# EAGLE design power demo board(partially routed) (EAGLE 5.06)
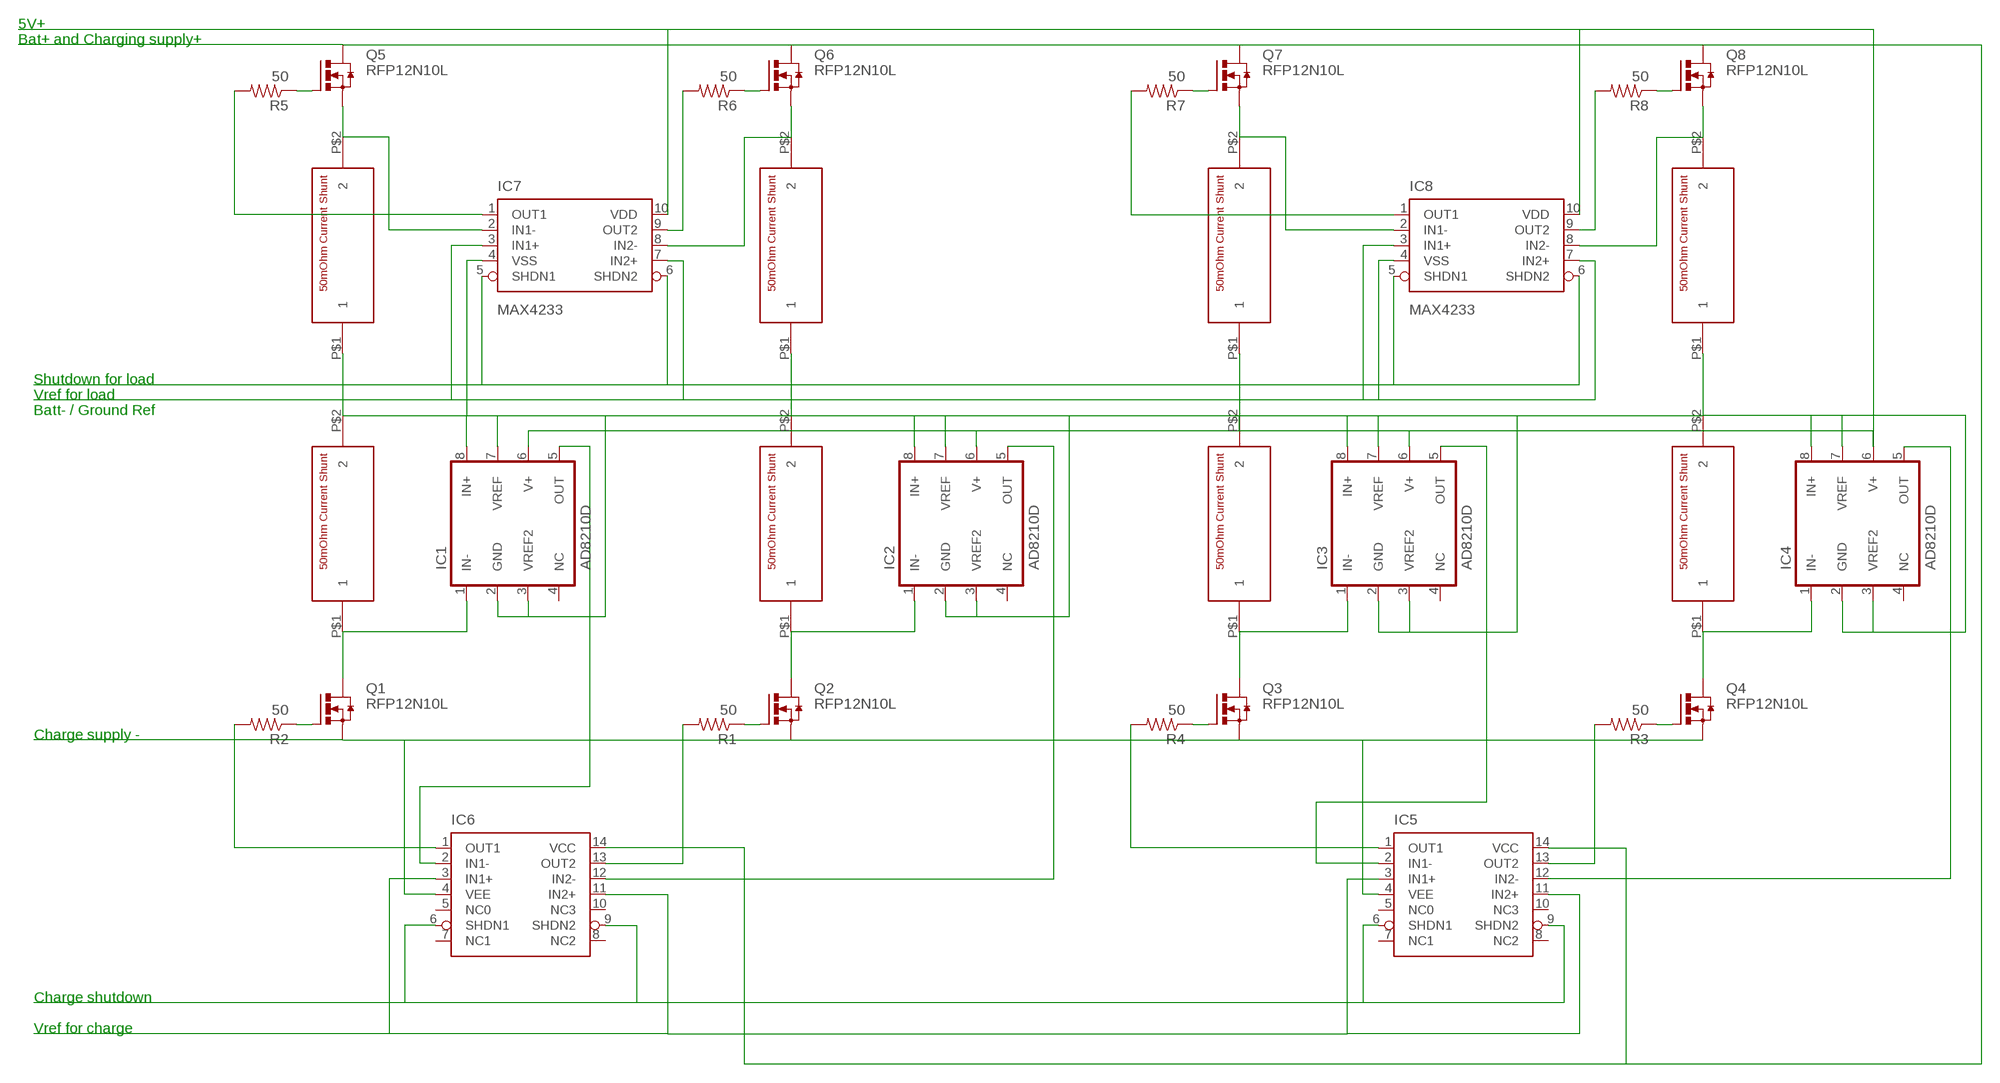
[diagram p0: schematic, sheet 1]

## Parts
IC1  AD8210D  [SO08]
IC2  AD8210D  [SO08]
IC3  AD8210D  [SO08]
IC4  AD8210D  [SO08]
IC5  MAX4168D  [SO14]
IC6  MAX4168D  [SO14]
IC7  MAX4233  [UMAX10]
IC8  MAX4233  [UMAX10]
Q1  RFP12N10L  [TO220-W/657-20ABP]
Q2  RFP12N10L  [TO220-W/657-20ABP]
Q3  RFP12N10L  [TO220-W/657-20ABP]
Q4  RFP12N10L  [TO220-W/657-20ABP]
Q5  RFP12N10L  [TO220-W/657-20ABP]
Q6  RFP12N10L  [TO220-W/657-20ABP]
Q7  RFP12N10L  [TO220-W/657-20ABP]
Q8  RFP12N10L  [TO220-W/657-20ABP]
R1  50  R-US_0207/10  [0207/10]
R2  50  R-US_0207/10  [0207/10]
R3  50  R-US_0207/10  [0207/10]
R4  50  R-US_0207/10  [0207/10]
R5  50  R-US_0207/10  [0207/10]
R6  50  R-US_0207/10  [0207/10]
R7  50  R-US_0207/10  [0207/10]
R8  50  R-US_0207/10  [0207/10]
U$1  630HR050E  [630HR050E]
U$2  630HR050E  [630HR050E]
U$3  630HR050E  [630HR050E]
U$4  630HR050E  [630HR050E]
U$5  630HR050E  [630HR050E]
U$6  630HR050E  [630HR050E]
U$7  630HR050E  [630HR050E]
U$8  630HR050E  [630HR050E]

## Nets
N$1: IC5.13(OUT2) R3.2
N$2: IC1.1(IN-) Q1.2(D) U$5.P$1
N$3: IC2.1(IN-) Q2.2(D) U$6.P$1
N$4: IC3.1(IN-) Q3.2(D) U$7.P$1
N$5: IC7.3(IN1+) IC7.7(IN2+) IC8.3(IN1+) IC8.4(VSS) IC8.7(IN2+)
N$6: IC5.4(VEE) IC6.4(VEE) Q1.3(S) Q2.3(S) Q3.3(S) Q4.3(S)
N$7: IC7.2(IN1-) Q5.3(S) U$1.P$2
N$8: IC7.8(IN2-) Q6.3(S) U$2.P$2
N$9: IC8.2(IN1-) Q7.3(S) U$3.P$2
N$10: IC8.8(IN2-) Q8.3(S) U$4.P$2
N$11: IC5.14(VCC) IC6.14(VCC) Q5.2(D) Q6.2(D) Q7.2(D) Q8.2(D)
N$12: IC7.1(OUT1) R5.2
N$13: Q5.1(G) R5.1
N$14: IC7.9(OUT2) R6.2
N$15: Q6.1(G) R6.1
N$16: Q7.1(G) R7.1
N$17: IC8.1(OUT1) R7.2
N$18: Q8.1(G) R8.1
N$19: IC8.9(OUT2) R8.2
N$20: IC7.5(SHDN1) IC7.6(SHDN2) IC8.5(SHDN1) IC8.6(SHDN2)
N$21: IC4.1(IN-) Q4.2(D) U$8.P$1
N$22: IC5.6(SHDN1) IC5.9(SHDN2) IC6.6(SHDN1) IC6.9(SHDN2)
N$23: IC6.13(OUT2) R1.2
N$24: Q1.1(G) R2.1
N$25: Q2.1(G) R1.1
N$26: Q3.1(G) R4.1
N$27: Q4.1(G) R3.1
N$28: IC5.1(OUT1) R4.2
N$29: IC2.5(OUT) IC6.12(IN2-)
N$31: IC5.3(IN1+) IC5.11(IN2+) IC6.3(IN1+) IC6.11(IN2+)
N$32: IC1.5(OUT) IC6.2(IN1-)
N$33: IC6.1(OUT1) R2.2
N$34: IC4.5(OUT) IC5.12(IN2-)
N$35: IC3.5(OUT) IC5.2(IN1-)
N$36: IC1.2(GND) IC1.3(VREF2) IC1.7(VREF) IC1.8(IN+) IC2.2(GND) IC2.3(VREF2) IC2.7(VREF) IC2.8(IN+) IC3.2(GND) IC3.3(VREF2) IC3.7(VREF) IC3.8(IN+) IC4.2(GND) IC4.3(VREF2) IC4.7(VREF) IC4.8(IN+) IC7.4(VSS) U$1.P$1 U$2.P$1 U$3.P$1 U$4.P$1 U$5.P$2 U$6.P$2 U$7.P$2 U$8.P$2
N$40: IC1.6(V+) IC2.6(V+) IC3.6(V+) IC4.6(V+) IC7.10(VDD) IC8.10(VDD)
Unconnected: IC5.5(NC0) IC5.7(NC1) IC5.10(NC3) IC6.5(NC0) IC6.7(NC1) IC6.10(NC3)

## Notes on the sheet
- 5V+
- Bat+ and Charging supply+
- Shutdown for load
- Vref for load
- Batt- / Ground Ref
- Charge supply -
- Charge shutdown
- Vref for charge

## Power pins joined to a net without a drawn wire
NC: IC1.4(NC) IC2.4(NC) IC3.4(NC) IC4.4(NC)
NC2: IC5.8(NC2) IC6.8(NC2)

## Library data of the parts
IC1-IC4 = NEWPARTS:AD8210: High Voltage, Bidirectional Current Shunt Monitor
IC5 IC6 = NEWPARTS:MAX4168: High-Output-Drive, Precision, Low-power, Single-Supply, Rail-to-Rail I/O Op Amps with Shutdown
IC7 IC8 = NEWPARTS:MAX4233: High-Output-Drive, 10MHz, 10V/us, Rail-to_rail I/O Op Amps with Shutdown in SC70
Q1-Q8 = NEWPARTS:RFP12N10L: N-Channel Power MOSFET 100V; 12A; 0,2Ohm< Logic Level
R1-R8 = rcl:R-US_: RESISTOR, American symbol
U$1-U$8 = NEWPARTS:630HR050E

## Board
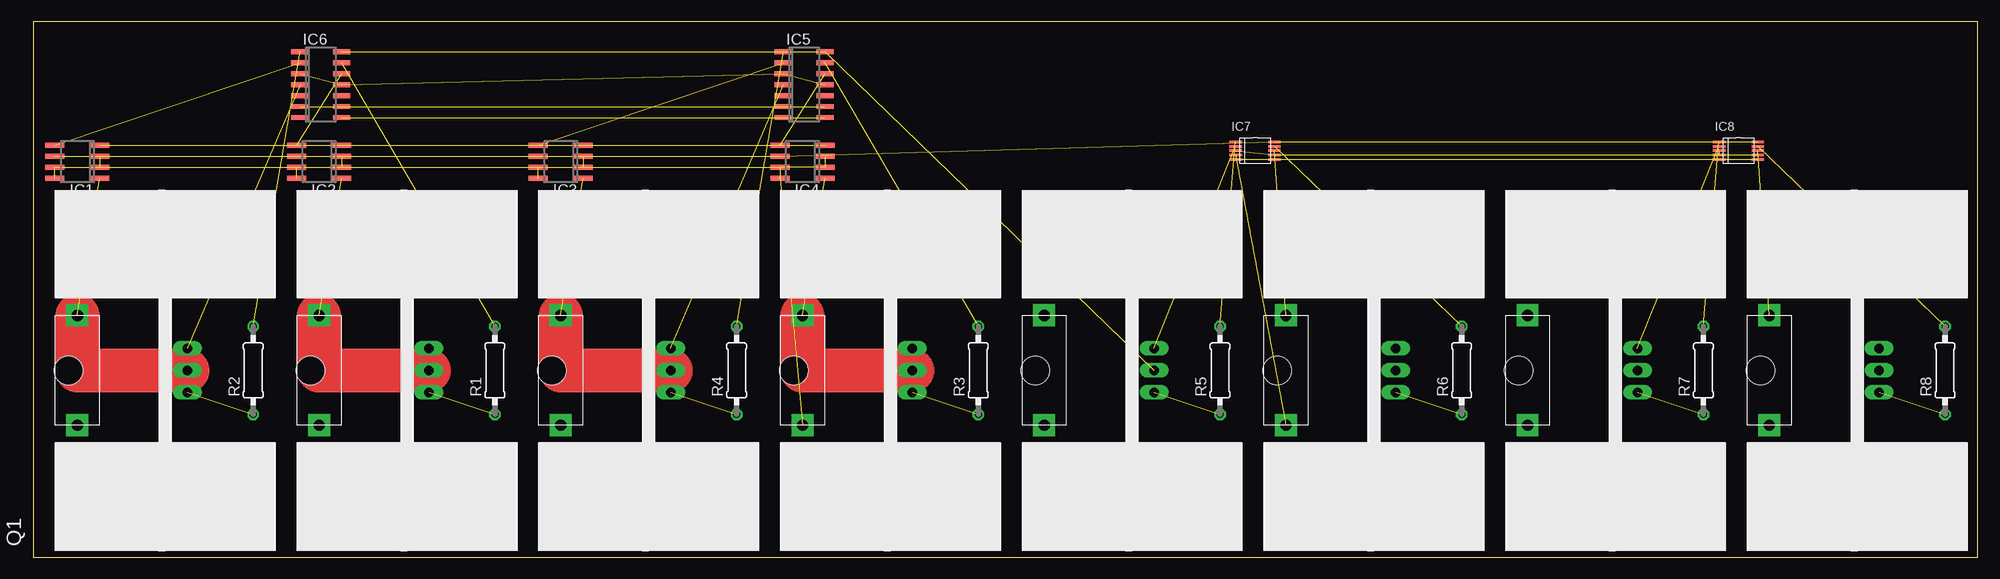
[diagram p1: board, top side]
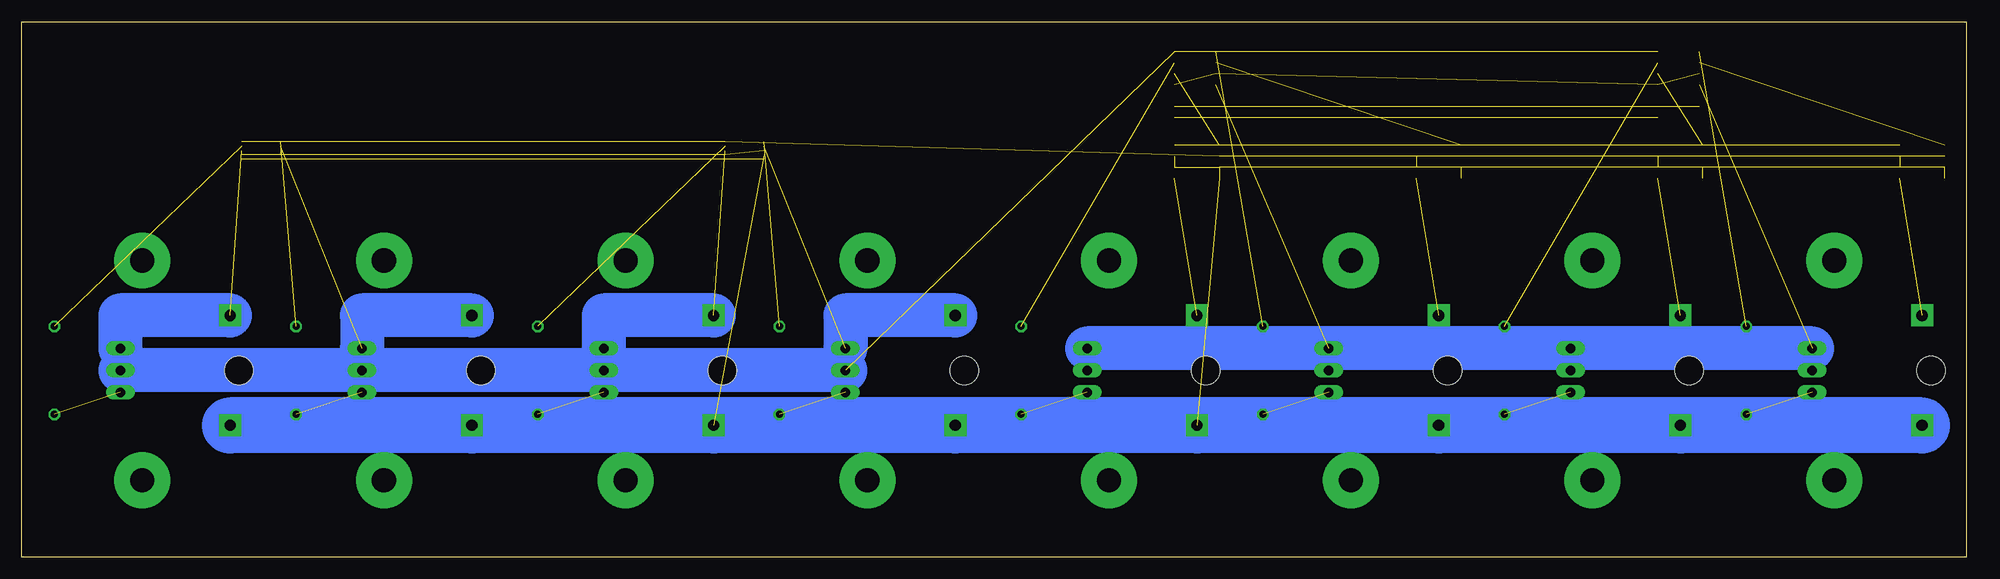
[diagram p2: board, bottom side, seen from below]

Size 224.77 x 61.9 mm. Coordinates in mm from the lower left corner, seen from the top.
Outline: 0,0 224.77,0 224.77,61.9 0,61.9 0,0
Copper layers (1*16): Top 0.035mm / dielectric 1.5mm / Bottom 0.035mm
Design rules "default": minimum track width 10mil, minimum drill 24mil, track to track 8mil, track to pad 8mil, pad to pad 8mil, via to via 8mil, smd to smd 8mil, copper to edge 40mil, drill to drill 8mil, minimum pad ring 10mil, minimum via ring 8mil, stop-mask expansion 4mil, vias tented up to drill 0mil, thermal gap 10mil

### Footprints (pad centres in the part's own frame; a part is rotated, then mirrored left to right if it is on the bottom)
SO08 = smd 0.6 x 2.2: 1 -1.905,-2.6; 2 -0.635,-2.6; 3 0.635,-2.6; 4 1.905,-2.6; 5 1.905,2.6; 6 0.635,2.6; 7 -0.635,2.6; 8 -1.905,2.6
SO14 = smd 0.533 x 1.981: 1 -3.81,-2.219; 2 -2.54,-2.219; 3 -1.27,-2.219; 4 0,-2.219; 5 1.27,-2.219; 6 2.54,-2.219; 7 3.81,-2.219; 8 3.81,2.6; 9 2.54,2.6; 10 1.27,2.6; 11 0,2.6; 12 -1.27,2.6; 13 -2.54,2.6; 14 -3.81,2.6
UMAX10 = smd 0.28 x 1.4: 1 -1,-2; 2 -0.5,-2; 3 0,-2; 4 0.5,-2; 5 1,-2; 6 1,2.5; 7 0.5,2.5; 8 0,2.5; 9 -0.5,2.5; 10 -1,2.5
TO220-W/657-20ABP = drill 1.118 long: 1 -2.54,-2.54; 2 0,-2.54; 3 2.54,-2.54 | drill 2.8 pad 6.452 round: P$1 -12.7,0; P$2 12.7,0 | hole 3.302: 0,11.176
0207/10 = drill 0.813 octagon: 1 -5.08,0; 2 5.08,0
630HR050E = drill 1.3 pad 2.54 square: P$1 -6.35,0; P$2 6.35,0

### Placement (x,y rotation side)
IC1  5.08,45.72 90 top
IC2  33.02,45.72 90 top
IC3  60.96,45.72 90 top
IC4  88.9,45.72 90 top
IC5  88.9,54.61 270 top
IC6  33.02,54.61 270 top
IC7  140.97,46.99 270 top
IC8  196.85,46.99 270 top
Q1  15.24,21.59 90 top
Q2  43.18,21.59 90 top
Q3  71.12,21.59 90 top
Q4  99.06,21.59 90 top
Q5  127,21.59 90 top
Q6  154.94,21.59 90 top
Q7  182.88,21.59 90 top
Q8  210.82,21.59 90 top
R1  53.34,21.59 90 top
R2  25.4,21.59 90 top
R3  109.22,21.59 90 top
R4  81.28,21.59 90 top
R5  137.16,21.59 90 top
R6  165.1,21.59 90 top
R7  193.04,21.59 90 top
R8  220.98,21.59 90 top
U$1  116.84,21.59 90 top
U$2  144.78,21.59 90 top
U$3  172.72,21.59 90 top
U$4  200.66,21.59 90 top
U$5  5.08,21.59 270 top
U$6  33.02,21.59 270 top
U$7  60.96,21.59 270 top
U$8  88.9,21.59 270 top

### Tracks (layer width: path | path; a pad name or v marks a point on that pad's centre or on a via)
N$1  (1 unrouted)
N$2  (1 unrouted)
  Top 5.08: U$5.P$1 5.08,21.59 Q1.2
N$3  (1 unrouted)
  Top 5.08: U$6.P$1 33.02,21.59 Q2.2
N$4  (1 unrouted)
  Top 5.08: U$7.P$1 60.96,21.59 Q3.2
N$5  (4 unrouted)
N$6  (2 unrouted)
  Bottom 5.08: Q1.3 Q2.3 Q3.3 Q4.3
N$7  (1 unrouted)
  Bottom 5.08: U$1.P$2 129.54,27.94 Q5.3
N$8  (1 unrouted)
  Bottom 5.08: U$2.P$2 157.48,27.94 Q6.3
N$9  (1 unrouted)
  Bottom 5.08: U$3.P$2 185.42,27.94 Q7.3
N$10  (1 unrouted)
  Bottom 5.08: U$4.P$2 213.36,27.94 Q8.3
N$11  (2 unrouted)
  Bottom 5.08: Q5.2 Q6.2 Q7.2 Q8.2
N$12  (1 unrouted)
N$13  (1 unrouted)
N$14  (1 unrouted)
N$15  (1 unrouted)
N$16  (1 unrouted)
N$17  (1 unrouted)
N$18  (1 unrouted)
N$19  (1 unrouted)
N$20  (3 unrouted)
N$21  (1 unrouted)
  Top 5.08: U$8.P$1 88.9,21.59 Q4.2
N$22  (3 unrouted)
N$23  (1 unrouted)
N$24  (1 unrouted)
N$25  (1 unrouted)
N$26  (1 unrouted)
N$27  (1 unrouted)
N$28  (1 unrouted)
N$29  (1 unrouted)
N$31  (3 unrouted)
N$32  (1 unrouted)
N$33  (1 unrouted)
N$34  (1 unrouted)
N$35  (1 unrouted)
N$36  (17 unrouted)
  Bottom 6.452: U$5.P$2 U$6.P$2 U$7.P$2 U$8.P$2 U$1.P$1 U$2.P$1 U$3.P$1 U$4.P$1
N$40  (5 unrouted)
NC  (3 unrouted)
NC2  (1 unrouted)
